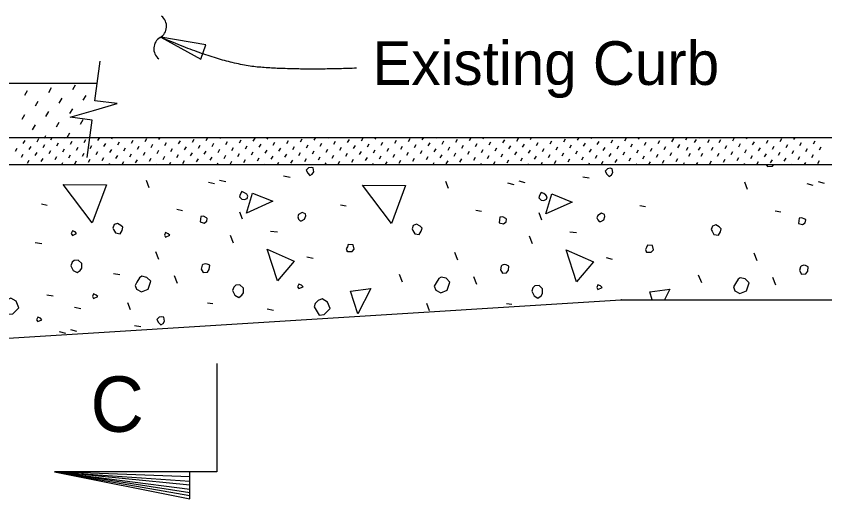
# Model space of a CAD drawing. Extents: x 1.5 to 68.7, y 0 to 31.1.
# Drawn here: x 6.295 to 10.034, y 9.315 to 11.544 of the extents above; entities that cross this region are included whole.
import ezdxf

# ---------------------------------------------------------------- set-up
doc = ezdxf.new("R2010")
doc.units = 0
for name, color, linetype in [('AdhocPoint_dp', 7, 'Continuous'), ('Patterning', 7, 'Continuous'), ('PlotBorder_dp', 7, 'Continuous'), ('SheetBorder_dp', 7, 'Continuous')]:
    doc.layers.add(name, color=color, linetype=linetype)

msp = doc.modelspace()

# ---------------------------------------------------------------- linework, layer by layer
at = {"layer": 'AdhocPoint_dp'}
for p, q in [((7.0977, 9.4172), (6.4727, 9.4405)), ((6.4727, 9.4405), (7.0977, 9.3972)), ((7.0977, 9.3788), (6.4727, 9.4405)), ((6.4727, 9.4405), (7.0977, 9.3605)), ((7.0977, 9.3438), (6.4727, 9.4405)), ((6.4727, 9.4405), (7.0977, 9.3305))]:
    msp.add_line(p, q, dxfattribs=at)
msp.add_lwpolyline([(6.9637, 11.4471), (7.1488, 11.3454), (7.172, 11.412)], close=True, dxfattribs=at)
for points in [[(6.6242, 10.8911), (6.6474, 11.0649), (6.5449, 11.0786), (6.6533, 11.1095), (6.7617, 11.1405), (6.6593, 11.1541), (6.6836, 11.3365)], [(7.2227, 9.9405), (7.2227, 9.4405), (6.4727, 9.4405), (7.0977, 9.3155), (7.0977, 9.4405)]]:
    msp.add_lwpolyline(points, dxfattribs=at)
for centre, start, end in [((6.9312, 11.4974), 300.2724, 51.9996), ((6.9913, 11.3945), 120.2724, 231.9996)]:
    msp.add_arc(centre, 0.0596, start, end, dxfattribs=at)
msp.add_open_spline([(7.8694, 11.304), (7.5929, 11.2944), (7.2496, 11.323), (6.9636, 11.4471)], degree=2, dxfattribs=at)
at = {"layer": 'Patterning'}
for p, q in [((6.5567, 11.2051), (6.5697, 11.2275)), ((6.3355, 11.1792), (6.3484, 11.2016)), ((6.4461, 11.1921), (6.4591, 11.2145)), ((6.3843, 11.1304), (6.3973, 11.1527)), ((6.4949, 11.1433), (6.5079, 11.1657)), ((6.6056, 11.1563), (6.6185, 11.1787)), ((6.5438, 11.0945), (6.5567, 11.1169)), ((6.3225, 11.0686), (6.3355, 11.0909)), ((6.4331, 11.0815), (6.4461, 11.1039)), ((6.5926, 11.0456), (6.6056, 11.068)), ((6.3713, 11.0197), (6.3843, 11.0421)), ((6.482, 11.0327), (6.4949, 11.0551)), ((6.4264, 10.9816), (6.4331, 10.9933)), ((6.5308, 10.9838), (6.5438, 11.0062)), ((6.3285, 10.9568), (6.3366, 10.9708)), ((6.392, 10.9649), (6.4001, 10.9789)), ((6.4555, 10.973), (6.4621, 10.9845)), ((6.4832, 10.9453), (6.4913, 10.9593)), ((6.519, 10.9811), (6.5209, 10.9845)), ((6.5467, 10.9534), (6.5548, 10.9674)), ((6.6102, 10.9616), (6.6183, 10.9755)), ((6.6274, 10.981), (6.6261, 10.9845)), ((6.6737, 10.9697), (6.6818, 10.9836)), ((6.7014, 10.942), (6.7095, 10.956)), ((6.7372, 10.9778), (6.7411, 10.9845)), ((6.7649, 10.9501), (6.773, 10.9641)), ((6.8283, 10.9582), (6.8364, 10.9722)), ((6.8918, 10.9663), (6.8999, 10.9803)), ((6.9553, 10.9744), (6.9612, 10.9845)), ((6.983, 10.9467), (6.9911, 10.9607)), ((7.0188, 10.9825), (7.02, 10.9845)), ((7.0465, 10.9548), (7.0546, 10.9688)), ((7.11, 10.9629), (7.1181, 10.9769)), ((7.1735, 10.971), (7.1813, 10.9845)), ((7.2012, 10.9433), (7.2093, 10.9573)), ((7.237, 10.9791), (7.2401, 10.9845)), ((7.2647, 10.9514), (7.2728, 10.9654)), ((7.3282, 10.9595), (7.3363, 10.9735)), ((7.3917, 10.9676), (7.3998, 10.9816)), ((7.4552, 10.9757), (7.4603, 10.9845)), ((7.4829, 10.948), (7.491, 10.962)), ((7.5187, 10.9838), (7.5191, 10.9845)), ((7.5464, 10.9561), (7.5545, 10.9701)), ((7.6098, 10.9642), (7.6179, 10.9782)), ((7.6733, 10.9723), (7.6804, 10.9845)), ((7.701, 10.9446), (7.7091, 10.9586)), ((7.7368, 10.9804), (7.7392, 10.9845)), ((7.7645, 10.9527), (7.7726, 10.9667)), ((7.828, 10.9608), (7.8361, 10.9748)), ((7.8915, 10.9689), (7.8996, 10.9829)), ((7.9192, 10.9412), (7.9273, 10.9552)), ((7.955, 10.977), (7.9593, 10.9845)), ((7.9827, 10.9493), (7.9908, 10.9633)), ((8.0462, 10.9574), (8.0543, 10.9714)), ((8.1097, 10.9655), (8.1178, 10.9795)), ((8.1732, 10.9736), (8.1795, 10.9845)), ((8.2009, 10.9459), (8.209, 10.9599)), ((8.2367, 10.9817), (8.2383, 10.9845)), ((8.2644, 10.954), (8.2725, 10.968)), ((8.3279, 10.9621), (8.336, 10.9761)), ((8.3913, 10.9702), (8.3994, 10.9842)), ((8.419, 10.9425), (8.4271, 10.9565)), ((8.4548, 10.9783), (8.4584, 10.9845)), ((8.4825, 10.9506), (8.4906, 10.9646)), ((8.546, 10.9588), (8.5541, 10.9727)), ((8.6095, 10.9669), (8.6176, 10.9808)), ((8.673, 10.975), (8.6785, 10.9845)), ((8.7007, 10.9473), (8.7088, 10.9613)), ((8.7365, 10.9831), (8.7373, 10.9845)), ((8.7642, 10.9554), (8.7723, 10.9694)), ((8.8277, 10.9635), (8.8358, 10.9775)), ((8.8912, 10.9716), (8.8987, 10.9845)), ((8.9189, 10.9439), (8.927, 10.9579)), ((8.9547, 10.9797), (8.9575, 10.9845)), ((8.9824, 10.952), (8.9905, 10.966)), ((9.0459, 10.9601), (9.054, 10.9741)), ((9.1094, 10.9682), (9.1175, 10.9822)), ((9.1728, 10.9763), (9.1776, 10.9845)), ((9.2005, 10.9486), (9.2086, 10.9626)), ((9.2363, 10.9844), (9.2364, 10.9845)), ((9.264, 10.9567), (9.2721, 10.9707)), ((9.3275, 10.9648), (9.3356, 10.9788)), ((9.391, 10.9729), (9.3977, 10.9845)), ((9.4322, 10.9614), (9.4403, 10.9754)), ((9.4545, 10.981), (9.4565, 10.9845)), ((9.4932, 10.9614), (9.5013, 10.9754)), ((9.5457, 10.9614), (9.5538, 10.9754)), ((9.6092, 10.9695), (9.6173, 10.9835)), ((9.6369, 10.9418), (9.645, 10.9558)), ((9.6727, 10.9776), (9.6767, 10.9845)), ((9.7004, 10.9499), (9.7085, 10.9639)), ((9.7639, 10.958), (9.772, 10.972)), ((9.8274, 10.9661), (9.8355, 10.9801)), ((9.8909, 10.9742), (9.8968, 10.9845)), ((9.9185, 10.9465), (9.9267, 10.9605)), ((9.9543, 10.9823), (9.9556, 10.9845)), ((9.982, 10.9546), (9.9901, 10.9686)), ((6.2927, 10.921), (6.3008, 10.935)), ((6.3562, 10.9291), (6.3643, 10.9431)), ((6.4197, 10.9372), (6.4278, 10.9512)), ((6.4474, 10.9095), (6.4555, 10.9235)), ((6.5109, 10.9177), (6.519, 10.9316)), ((6.5744, 10.9258), (6.5825, 10.9397)), ((6.6379, 10.9339), (6.646, 10.9479)), ((6.6656, 10.9062), (6.6737, 10.9202)), ((6.7291, 10.9143), (6.7372, 10.9283)), ((6.7925, 10.9224), (6.8006, 10.9364)), ((6.856, 10.9305), (6.8641, 10.9445)), ((6.9195, 10.9386), (6.9276, 10.9526)), ((6.9472, 10.9109), (6.9553, 10.9249)), ((7.0107, 10.919), (7.0188, 10.933)), ((7.0742, 10.9271), (7.0823, 10.9411)), ((7.1377, 10.9352), (7.1458, 10.9492)), ((7.1654, 10.9075), (7.1735, 10.9215)), ((7.2289, 10.9156), (7.237, 10.9296)), ((7.2924, 10.9237), (7.3005, 10.9377)), ((7.3559, 10.9318), (7.364, 10.9458)), ((7.3836, 10.9041), (7.3917, 10.9181)), ((7.4194, 10.9399), (7.4275, 10.9539)), ((7.4471, 10.9122), (7.4552, 10.9262)), ((7.5106, 10.9203), (7.5187, 10.9343)), ((7.574, 10.9284), (7.5821, 10.9424)), ((7.6375, 10.9365), (7.6456, 10.9505)), ((7.6652, 10.9088), (7.6733, 10.9228)), ((7.7287, 10.9169), (7.7368, 10.9309)), ((7.7922, 10.925), (7.8003, 10.939)), ((7.8557, 10.9331), (7.8638, 10.9471)), ((7.8834, 10.9054), (7.8915, 10.9194)), ((7.9469, 10.9135), (7.955, 10.9275)), ((8.0104, 10.9216), (8.0185, 10.9356)), ((8.0739, 10.9297), (8.082, 10.9437)), ((8.1374, 10.9378), (8.1455, 10.9518)), ((8.1651, 10.9101), (8.1732, 10.9241)), ((8.2286, 10.9182), (8.2367, 10.9322)), ((8.2921, 10.9263), (8.3002, 10.9403)), ((8.3555, 10.9344), (8.3636, 10.9484)), ((8.3832, 10.9067), (8.3913, 10.9207)), ((8.4467, 10.9149), (8.4548, 10.9288)), ((8.5102, 10.923), (8.5183, 10.9369)), ((8.5737, 10.9311), (8.5818, 10.9451)), ((8.6014, 10.9034), (8.6095, 10.9174)), ((8.6372, 10.9392), (8.6453, 10.9532)), ((8.6649, 10.9115), (8.673, 10.9255)), ((8.7284, 10.9196), (8.7365, 10.9336)), ((8.7919, 10.9277), (8.8, 10.9417)), ((8.8554, 10.9358), (8.8635, 10.9498)), ((8.8831, 10.9081), (8.8912, 10.9221)), ((8.9466, 10.9162), (8.9547, 10.9302)), ((9.0101, 10.9243), (9.0182, 10.9383)), ((9.0736, 10.9324), (9.0817, 10.9464)), ((9.1013, 10.9047), (9.1094, 10.9187)), ((9.137, 10.9405), (9.1451, 10.9545)), ((9.1647, 10.9128), (9.1728, 10.9268)), ((9.2282, 10.9209), (9.2363, 10.9349)), ((9.2917, 10.929), (9.2998, 10.943)), ((9.3552, 10.9371), (9.3633, 10.9511)), ((9.3948, 10.9256), (9.4029, 10.9396)), ((9.4506, 10.9256), (9.4587, 10.9396)), ((9.5099, 10.9256), (9.518, 10.9396)), ((9.5734, 10.9337), (9.5815, 10.9477)), ((9.6011, 10.906), (9.6092, 10.92)), ((9.6646, 10.9141), (9.6727, 10.9281)), ((9.7281, 10.9222), (9.7362, 10.9362)), ((9.7916, 10.9303), (9.7997, 10.9443)), ((9.8551, 10.9384), (9.8632, 10.9524)), ((9.8828, 10.9107), (9.8909, 10.9247)), ((9.9462, 10.9188), (9.9543, 10.9328)), ((10.0097, 10.9269), (10.0178, 10.9409)), ((6.3204, 10.8933), (6.3285, 10.9073)), ((6.3839, 10.9014), (6.392, 10.9154)), ((6.4116, 10.8738), (6.4197, 10.8877)), ((6.4751, 10.8819), (6.4832, 10.8958)), ((6.5386, 10.89), (6.5467, 10.904)), ((6.6021, 10.8981), (6.6102, 10.9121)), ((6.6298, 10.8704), (6.6379, 10.8844)), ((6.6933, 10.8785), (6.7014, 10.8925)), ((6.7567, 10.8866), (6.7649, 10.9006)), ((6.8202, 10.8947), (6.8283, 10.9087)), ((6.8479, 10.867), (6.856, 10.881)), ((6.8837, 10.9028), (6.8918, 10.9168)), ((6.9114, 10.8751), (6.9195, 10.8891)), ((6.9749, 10.8832), (6.983, 10.8972)), ((7.0384, 10.8913), (7.0465, 10.9053)), ((7.1019, 10.8994), (7.11, 10.9134)), ((7.1296, 10.8717), (7.1377, 10.8857)), ((7.1931, 10.8798), (7.2012, 10.8938)), ((7.2566, 10.8879), (7.2647, 10.9019)), ((7.3201, 10.896), (7.3282, 10.91)), ((7.3478, 10.8683), (7.3559, 10.8823)), ((7.4113, 10.8764), (7.4194, 10.8904)), ((7.4748, 10.8845), (7.4829, 10.8985)), ((7.5382, 10.8926), (7.5464, 10.9066)), ((7.6017, 10.9007), (7.6098, 10.9147)), ((7.6294, 10.873), (7.6375, 10.887)), ((7.6929, 10.8811), (7.701, 10.8951)), ((7.7564, 10.8892), (7.7645, 10.9032)), ((7.8199, 10.8973), (7.828, 10.9113)), ((7.8476, 10.8696), (7.8557, 10.8836)), ((7.9111, 10.8777), (7.9192, 10.8917)), ((7.9746, 10.8858), (7.9827, 10.8998)), ((8.0381, 10.8939), (8.0462, 10.9079)), ((8.0658, 10.8662), (8.0739, 10.8802)), ((8.1016, 10.902), (8.1097, 10.916)), ((8.1293, 10.8743), (8.1374, 10.8883)), ((8.1928, 10.8824), (8.2009, 10.8964)), ((8.2563, 10.8905), (8.2644, 10.9045)), ((8.3198, 10.8986), (8.3279, 10.9126)), ((8.3474, 10.871), (8.3555, 10.8849)), ((8.4109, 10.8791), (8.419, 10.893)), ((8.4744, 10.8872), (8.4825, 10.9012)), ((8.5379, 10.8953), (8.546, 10.9093)), ((8.5656, 10.8676), (8.5737, 10.8816)), ((8.6291, 10.8757), (8.6372, 10.8897)), ((8.6926, 10.8838), (8.7007, 10.8978)), ((8.7561, 10.8919), (8.7642, 10.9059)), ((8.8196, 10.9), (8.8277, 10.914)), ((8.8473, 10.8723), (8.8554, 10.8863)), ((8.9108, 10.8804), (8.9189, 10.8944)), ((8.9743, 10.8885), (8.9824, 10.9025)), ((9.0378, 10.8966), (9.0459, 10.9106)), ((9.0655, 10.8689), (9.0736, 10.8829)), ((9.1289, 10.877), (9.137, 10.891)), ((9.1924, 10.8851), (9.2005, 10.8991)), ((9.2559, 10.8932), (9.264, 10.9072)), ((9.3194, 10.9013), (9.3275, 10.9153)), ((9.3471, 10.8736), (9.3552, 10.8876)), ((9.4055, 10.8979), (9.4136, 10.9119)), ((9.4626, 10.8979), (9.4708, 10.9119)), ((9.5376, 10.8979), (9.5457, 10.9119)), ((9.5653, 10.8702), (9.5734, 10.8842)), ((9.6288, 10.8783), (9.6369, 10.8923)), ((9.6923, 10.8864), (9.7004, 10.9004)), ((9.7558, 10.8945), (9.7639, 10.9085)), ((9.7835, 10.8668), (9.7916, 10.8808)), ((9.8193, 10.9026), (9.8274, 10.9166)), ((9.847, 10.8749), (9.8551, 10.8889)), ((9.9104, 10.883), (9.9185, 10.897)), ((9.9739, 10.8911), (9.982, 10.9051)), ((6.3481, 10.8656), (6.3562, 10.8796)), ((6.4471, 10.8595), (6.4474, 10.8601)), ((6.5059, 10.8595), (6.5109, 10.8682)), ((6.5663, 10.8623), (6.5744, 10.8763)), ((6.726, 10.8595), (6.7291, 10.8648)), ((6.7848, 10.8595), (6.7925, 10.8729)), ((6.9461, 10.8595), (6.9472, 10.8614)), ((7.0049, 10.8595), (7.0107, 10.8695)), ((7.0661, 10.8636), (7.0742, 10.8776)), ((7.2251, 10.8595), (7.2289, 10.8661)), ((7.2843, 10.8602), (7.2924, 10.8742)), ((7.4452, 10.8595), (7.4471, 10.8627)), ((7.504, 10.8595), (7.5106, 10.8708)), ((7.5659, 10.8649), (7.574, 10.8789)), ((7.7241, 10.8595), (7.7287, 10.8674)), ((7.7841, 10.8615), (7.7922, 10.8755)), ((7.9443, 10.8595), (7.9469, 10.864)), ((8.0031, 10.8595), (8.0104, 10.8721)), ((8.1644, 10.8595), (8.1651, 10.8606)), ((8.2232, 10.8595), (8.2286, 10.8687)), ((8.284, 10.8629), (8.2921, 10.8768)), ((8.4433, 10.8595), (8.4467, 10.8654)), ((8.5021, 10.8595), (8.5102, 10.8735)), ((8.6635, 10.8595), (8.6649, 10.862)), ((8.7223, 10.8595), (8.7284, 10.8701)), ((8.7838, 10.8642), (8.7919, 10.8782)), ((8.9424, 10.8595), (8.9466, 10.8667)), ((9.002, 10.8608), (9.0101, 10.8748)), ((9.1625, 10.8595), (9.1647, 10.8633)), ((9.2213, 10.8595), (9.2282, 10.8714)), ((9.2836, 10.8655), (9.2917, 10.8795)), ((9.381, 10.8595), (9.386, 10.868)), ((9.3827, 10.8595), (9.3829, 10.8599)), ((9.4415, 10.8595), (9.4464, 10.868)), ((9.5018, 10.8621), (9.5099, 10.8761)), ((9.6616, 10.8595), (9.6646, 10.8646)), ((9.7204, 10.8595), (9.7281, 10.8727)), ((9.8817, 10.8595), (9.8828, 10.8612)), ((9.9405, 10.8595), (9.9462, 10.8693)), ((10.0016, 10.8634), (10.0097, 10.8774)), ((7.5318, 10.8065), (7.5619, 10.8012)), ((6.9105, 10.7517), (6.8981, 10.7852)), ((7.1845, 10.7782), (7.2128, 10.7711)), ((7.2362, 10.7875), (7.2645, 10.7804)), ((8.2938, 10.7481), (8.2814, 10.7817)), ((8.5678, 10.7746), (8.596, 10.7676)), ((8.6195, 10.7839), (8.6477, 10.7768)), ((8.9151, 10.8029), (8.9452, 10.7976)), ((9.677, 10.7446), (9.6647, 10.7782)), ((9.951, 10.7711), (9.9793, 10.764)), ((10.0027, 10.7804), (10.031, 10.7733)), ((6.412, 10.6774), (6.4385, 10.6721)), ((7.7952, 10.6739), (7.8218, 10.6686)), ((9.1785, 10.6703), (9.205, 10.665)), ((7.0378, 10.6527), (7.0643, 10.6474)), ((7.3423, 10.6063), (7.3299, 10.6398)), ((8.421, 10.6491), (8.4475, 10.6438)), ((8.7255, 10.6027), (8.7132, 10.6363)), ((9.8043, 10.6456), (9.8308, 10.6403)), ((7.4717, 10.5519), (7.5036, 10.5484)), ((8.855, 10.5484), (8.8868, 10.5448)), ((7.2998, 10.4967), (7.2857, 10.532)), ((8.6831, 10.4931), (8.669, 10.5285)), ((6.3839, 10.4998), (6.4139, 10.4945)), ((6.9547, 10.4211), (6.9405, 10.4564)), ((7.6397, 10.4335), (7.668, 10.4264)), ((8.3379, 10.4175), (8.3238, 10.4529)), ((9.7212, 10.414), (9.7071, 10.4494)), ((9.023, 10.4299), (9.0512, 10.4229)), ((6.7449, 10.3562), (6.7749, 10.3509)), ((7.0417, 10.3093), (7.0276, 10.3446)), ((8.0816, 10.3168), (8.0675, 10.3521)), ((8.425, 10.3057), (8.4109, 10.3411)), ((9.4649, 10.3132), (9.4508, 10.3486)), ((9.8083, 10.3022), (9.7941, 10.3376)), ((6.4372, 10.2577), (6.4672, 10.2524)), ((6.8239, 10.1877), (6.8115, 10.2213)), ((7.1796, 10.2209), (7.2044, 10.2173)), ((8.2071, 10.1842), (8.1948, 10.2178)), ((8.5629, 10.2173), (8.5876, 10.2138)), ((6.5644, 10.2002), (6.5944, 10.1949)), ((7.4554, 10.1926), (7.4854, 10.1873)), ((6.5463, 10.0976), (6.5746, 10.0905)), ((6.842, 10.1166), (6.872, 10.1113)), ((6.4946, 10.0883), (6.5229, 10.0812))]:
    msp.add_line(p, q, dxfattribs=at)
for points in [[(7.6432, 10.8188), (7.6538, 10.8082), (7.6644, 10.8153), (7.6715, 10.8259), (7.668, 10.8436), (7.6591, 10.8453), (7.6467, 10.8436), (7.6361, 10.833), (7.6432, 10.8188)], [(9.7635, 10.8594), (9.769, 10.8507), (9.7919, 10.8524), (9.7989, 10.8594)], [(9.0265, 10.8153), (9.0371, 10.8047), (9.0477, 10.8118), (9.0548, 10.8224), (9.0512, 10.84), (9.0424, 10.8418), (9.03, 10.84), (9.0194, 10.8294), (9.0265, 10.8153)], [(6.6471, 10.5908), (6.5127, 10.7676), (6.7125, 10.7658), (6.6471, 10.5908)], [(7.3387, 10.6991), (7.3511, 10.6973), (7.3635, 10.7026), (7.367, 10.7132), (7.3617, 10.722), (7.3511, 10.7291), (7.3387, 10.7344), (7.3316, 10.7203), (7.3281, 10.7097), (7.3387, 10.6991)], [(8.0304, 10.5873), (7.896, 10.764), (8.0958, 10.7623), (8.0304, 10.5873)], [(8.722, 10.6955), (8.7344, 10.6938), (8.7467, 10.6991), (8.7503, 10.7097), (8.745, 10.7185), (8.7344, 10.7256), (8.722, 10.7309), (8.7149, 10.7167), (8.7114, 10.7061), (8.722, 10.6955)], [(7.3604, 10.635), (7.3887, 10.7269), (7.4823, 10.6898), (7.3604, 10.635)], [(8.7436, 10.6314), (8.7719, 10.7234), (8.8656, 10.6862), (8.7436, 10.6314)], [(7.1456, 10.5943), (7.165, 10.589), (7.1774, 10.5979), (7.1792, 10.6102), (7.1756, 10.6138), (7.1615, 10.6208), (7.1491, 10.6191), (7.1474, 10.6067), (7.1456, 10.5943)], [(7.6079, 10.5996), (7.6149, 10.5996), (7.6291, 10.6067), (7.6344, 10.6226), (7.6326, 10.6314), (7.6185, 10.6385), (7.6008, 10.6279), (7.5973, 10.6173), (7.6008, 10.6067), (7.6079, 10.5996)], [(8.9911, 10.5961), (8.9982, 10.5961), (9.0123, 10.6032), (9.0177, 10.6191), (9.0159, 10.6279), (9.0017, 10.635), (8.9841, 10.6244), (8.9805, 10.6138), (8.9841, 10.6032), (8.9911, 10.5961)], [(6.7461, 10.559), (6.7549, 10.5431), (6.7761, 10.5395), (6.785, 10.5554), (6.7885, 10.5696), (6.7797, 10.5784), (6.7637, 10.5873), (6.7478, 10.582), (6.7425, 10.566), (6.7461, 10.559)], [(8.1293, 10.5554), (8.1382, 10.5395), (8.1594, 10.536), (8.1682, 10.5519), (8.1718, 10.566), (8.1629, 10.5749), (8.147, 10.5837), (8.1311, 10.5784), (8.1258, 10.5625), (8.1293, 10.5554)], [(8.5289, 10.5908), (8.5483, 10.5855), (8.5607, 10.5943), (8.5625, 10.6067), (8.5589, 10.6102), (8.5448, 10.6173), (8.5324, 10.6155), (8.5306, 10.6032), (8.5289, 10.5908)], [(9.9121, 10.5873), (9.9316, 10.582), (9.944, 10.5908), (9.9457, 10.6032), (9.9422, 10.6067), (9.9281, 10.6138), (9.9157, 10.612), (9.9139, 10.5996), (9.9121, 10.5873)], [(6.5552, 10.532), (6.5747, 10.5408), (6.5676, 10.5479), (6.5552, 10.5532), (6.5499, 10.5408), (6.5552, 10.532)], [(6.9859, 10.5238), (7.0054, 10.5326), (6.9983, 10.5397), (6.9859, 10.545), (6.9806, 10.5326), (6.9859, 10.5238)], [(9.5126, 10.5519), (9.5215, 10.536), (9.5427, 10.5325), (9.5515, 10.5484), (9.5551, 10.5625), (9.5462, 10.5713), (9.5303, 10.5802), (9.5144, 10.5749), (9.5091, 10.559), (9.5126, 10.5519)], [(7.8271, 10.4582), (7.8483, 10.4582), (7.8589, 10.4688), (7.8536, 10.4883), (7.8306, 10.49), (7.8271, 10.4794), (7.8218, 10.4706), (7.8271, 10.4582), (7.8235, 10.4617)], [(9.2103, 10.4547), (9.2316, 10.4547), (9.2422, 10.4653), (9.2369, 10.4847), (9.2139, 10.4865), (9.2103, 10.4759), (9.205, 10.467), (9.2103, 10.4547), (9.2068, 10.4582)], [(7.5031, 10.3216), (7.4554, 10.4684), (7.5809, 10.4136), (7.5031, 10.3216)], [(8.8864, 10.3181), (8.8387, 10.4648), (8.9642, 10.41), (8.8864, 10.3181)], [(6.5488, 10.3918), (6.5594, 10.3706), (6.5771, 10.36), (6.5913, 10.3706), (6.5983, 10.3812), (6.5983, 10.4024), (6.5824, 10.4183), (6.563, 10.4165), (6.5541, 10.4077), (6.5488, 10.3918)], [(7.1513, 10.3764), (7.1602, 10.3605), (7.1796, 10.3623), (7.1885, 10.3747), (7.1902, 10.3941), (7.1778, 10.3994), (7.169, 10.4012), (7.1584, 10.3977), (7.1549, 10.3941), (7.1513, 10.3764)], [(8.5346, 10.3729), (8.5434, 10.357), (8.5629, 10.3588), (8.5717, 10.3711), (8.5735, 10.3906), (8.5611, 10.3959), (8.5523, 10.3977), (8.5417, 10.3941), (8.5381, 10.3906), (8.5346, 10.3729)], [(9.9179, 10.3694), (9.9267, 10.3535), (9.9462, 10.3552), (9.955, 10.3676), (9.9568, 10.3871), (9.9444, 10.3924), (9.9356, 10.3941), (9.925, 10.3906), (9.9214, 10.3871), (9.9179, 10.3694)], [(6.8521, 10.2832), (6.8751, 10.2708), (6.9052, 10.2832), (6.9175, 10.3203), (6.8999, 10.338), (6.8769, 10.3433), (6.8663, 10.3362), (6.8539, 10.3168), (6.8451, 10.3009), (6.8521, 10.2832)], [(8.2354, 10.2797), (8.2584, 10.2673), (8.2884, 10.2797), (8.3008, 10.3168), (8.2831, 10.3345), (8.2602, 10.3398), (8.2496, 10.3327), (8.2372, 10.3132), (8.2283, 10.2973), (8.2354, 10.2797)], [(9.6187, 10.2761), (9.6417, 10.2638), (9.6717, 10.2761), (9.6841, 10.3132), (9.6664, 10.3309), (9.6434, 10.3362), (9.6328, 10.3292), (9.6205, 10.3097), (9.6116, 10.2938), (9.6187, 10.2761)], [(7.2963, 10.2775), (7.3069, 10.2562), (7.3246, 10.2456), (7.3387, 10.2562), (7.3458, 10.2668), (7.3458, 10.2881), (7.3299, 10.304), (7.3104, 10.3022), (7.3016, 10.2934), (7.2963, 10.2775)], [(7.6021, 10.2863), (7.6216, 10.2951), (7.6145, 10.3022), (7.6021, 10.3075), (7.5968, 10.2951), (7.6021, 10.2863)], [(7.8748, 10.1701), (7.8412, 10.2744), (7.9349, 10.2867), (7.8748, 10.1701)], [(8.6796, 10.2739), (8.6902, 10.2527), (8.7079, 10.2421), (8.722, 10.2527), (8.7291, 10.2633), (8.7291, 10.2845), (8.7132, 10.3004), (8.6937, 10.2987), (8.6849, 10.2898), (8.6796, 10.2739)], [(8.9854, 10.2828), (9.0048, 10.2916), (8.9978, 10.2987), (8.9854, 10.304), (8.9801, 10.2916), (8.9854, 10.2828)], [(9.2362, 10.2344), (9.2245, 10.2708), (9.3182, 10.2832), (9.2931, 10.2344)], [(6.6537, 10.2406), (6.6731, 10.2494), (6.666, 10.2565), (6.6537, 10.2618), (6.6484, 10.2494), (6.6537, 10.2406)], [(6.2339, 10.205), (6.2568, 10.1679), (6.2798, 10.1696), (6.2887, 10.1785), (6.3081, 10.1979), (6.2957, 10.228), (6.271, 10.2421), (6.2533, 10.235), (6.2392, 10.2209), (6.2339, 10.205)], [(7.6728, 10.2014), (7.6958, 10.1643), (7.7188, 10.1661), (7.7276, 10.1749), (7.7471, 10.1944), (7.7347, 10.2244), (7.7099, 10.2386), (7.6923, 10.2315), (7.6781, 10.2173), (7.6728, 10.2014)], [(9.0942, 10.2344), (9.0932, 10.235), (9.0918, 10.2344)], [(6.3952, 10.1339), (6.4147, 10.1427), (6.4076, 10.1498), (6.3952, 10.1551), (6.3899, 10.1427), (6.3952, 10.1339)], [(6.9533, 10.129), (6.9639, 10.1184), (6.9746, 10.1254), (6.9816, 10.136), (6.9781, 10.1537), (6.9693, 10.1555), (6.9569, 10.1537), (6.9463, 10.1431), (6.9533, 10.129)]]:
    msp.add_lwpolyline(points, dxfattribs=at)
at = {"layer": 'PlotBorder_dp'}
for p, q in [((4.4082, 11.2345), (6.67, 11.2345)), ((3.8717, 10.9845), (18.1441, 10.9845)), ((5.8718, 10.8595), (11.8162, 10.8595)), ((5.0917, 9.9844), (9.0917, 10.2344)), ((9.0917, 10.2345), (18.1442, 10.2345))]:
    msp.add_line(p, q, dxfattribs=at)

# ---------------------------------------------------------------- texts
at = {"layer": 'SheetBorder_dp'}
for s, height, p in [('Existing Curb', 0.2016, (7.9428, 11.227)), ('C', 0.256, (6.6388, 9.6249))]:
    msp.add_text(s, height=height, dxfattribs=at).set_placement(p)

doc.saveas('drawing.dxf')
